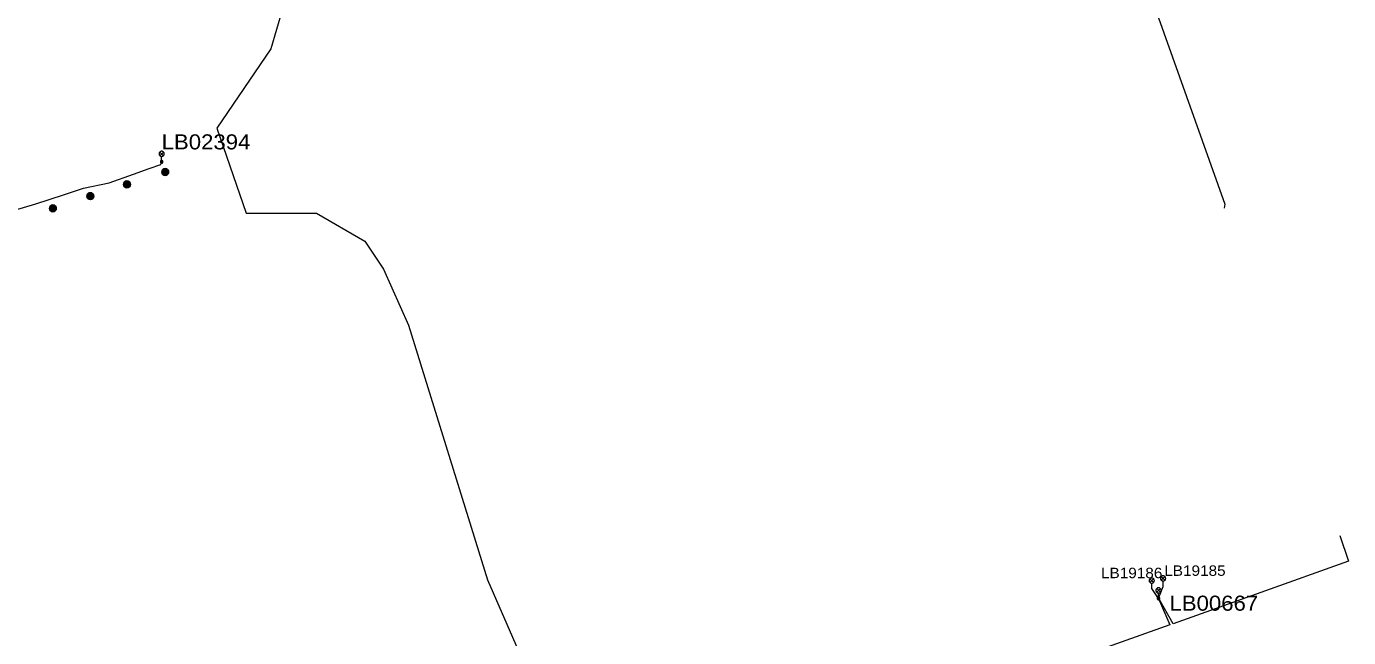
# Model space of a CAD drawing. Extents: x -688049 to -687261, y -973611 to -973038.
# Drawn here: x -687451.2 to -687260.9, y -973412.5 to -973324.5 of the extents above; entities that cross this region are included whole.
import ezdxf

# ---------------------------------------------------------------- set-up
doc = ezdxf.new("R2010")
doc.units = 0
doc.header["$LTSCALE"] = 0.87
doc.linetypes.add('LONG_DASH_SHORT_DASH', pattern=[9.9, 6, -1.2, 1.5, -1.2])
doc.layers.add('1', color=7, linetype='Continuous', lineweight=13)

msp = doc.modelspace()

# ---------------------------------------------------------------- hatches: boundary and pattern name
at = {"layer": '1'}
for points in [[(-687431.059, -973345.922, 1), (-687431.357, -973344.977, 1)], [(-687436.562, -973347.698, 1), (-687436.861, -973346.754, 1)], [(-687441.836, -973349.392, 1), (-687442.135, -973348.448, 1)], [(-687447.233, -973351.151, 1), (-687447.532, -973350.207, 1)]]:
    msp.add_hatch(color=256, dxfattribs=at).paths.add_polyline_path(points)

# ---------------------------------------------------------------- linework, layer by layer
for p, q in [((-687431.985, -973342.565), (-687431.455, -973343.095)), ((-687431.985, -973343.095), (-687431.455, -973342.565)), ((-687431.72, -973343.98), (-687431.72, -973343.205)), ((-687289.461, -973404.01), (-687288.931, -973404.54)), ((-687289.461, -973404.54), (-687288.931, -973404.01)), ((-687289.196, -973405.425), (-687289.196, -973404.65)), ((-687288.22, -973406.83), (-687287.559, -973405.098)), ((-687287.824, -973403.683), (-687287.294, -973404.213)), ((-687287.824, -973404.213), (-687287.294, -973403.683)), ((-687287.559, -973405.098), (-687287.559, -973404.323)), ((-687288.22, -973406.83), (-687289.196, -973405.425)), ((-687288.485, -973405.415), (-687287.955, -973405.945)), ((-687288.485, -973405.945), (-687287.955, -973405.415)), ((-687288.22, -973406.83), (-687288.22, -973406.055))]:
    msp.add_line(p, q, dxfattribs=at)
for points in [[(-687380.798, -973246.294), (-687379.608, -973246.294), (-687378.955, -973247.562), (-687376.887, -973255.287), (-687406.818, -973265.671), (-687416.352, -973274.485), (-687413.576, -973311.675), (-687413.576, -973319.312), (-687415.981, -973327.719), (-687423.796, -973339.13), (-687419.572, -973351.385), (-687409.434, -973351.385), (-687402.464, -973355.4), (-687399.787, -973359.445), (-687396.201, -973367.518), (-687384.836, -973404.179), (-687376.008, -973424.395), (-687374.353, -973427.776), (-687369.362, -973427.776), (-687366.818, -973426.737), (-687366.538, -973425.138)], [(-687288.9, -973322.19), (-687288.451, -973322.592), (-687278.691, -973350.089), (-687278.75, -973350.656)], [(-687262.11, -973397.78), (-687260.862, -973401.463), (-687286.115, -973410.499), (-687288.185, -973406.865)], [(-687288.22, -973406.83), (-687286.589, -973410.657), (-687312.448, -973419.852), (-687314.25, -973415.96)]]:
    msp.add_lwpolyline(points, dxfattribs=at)
at = {"layer": '1', "linetype": 'LONG_DASH_SHORT_DASH'}
msp.add_lwpolyline([(-687471.1, -973357.3), (-687469.23, -973356.72), (-687466.28, -973355.69), (-687461.51, -973353.91), (-687455.96, -973351.99), (-687452.92, -973350.95), (-687449.84, -973350.04), (-687445.86, -973348.71), (-687442.97, -973347.78), (-687439.3, -973347.01), (-687435.78, -973345.76), (-687433.52, -973344.93), (-687431.83, -973344.36), (-687431.72, -973343.98)], dxfattribs=at)
at = {"layer": '1'}
for points in [[(-687431.345, -973342.83), (-687431.351, -973342.765), (-687431.368, -973342.702), (-687431.395, -973342.643), (-687431.433, -973342.589), (-687431.479, -973342.543), (-687431.532, -973342.505), (-687431.592, -973342.478), (-687431.655, -973342.461), (-687431.72, -973342.455), (-687431.785, -973342.461), (-687431.848, -973342.478), (-687431.908, -973342.505), (-687431.961, -973342.543), (-687432.007, -973342.589), (-687432.045, -973342.643), (-687432.072, -973342.702), (-687432.089, -973342.765), (-687432.095, -973342.83), (-687432.089, -973342.895), (-687432.072, -973342.958), (-687432.045, -973343.018), (-687432.007, -973343.071), (-687431.961, -973343.117), (-687431.908, -973343.155), (-687431.848, -973343.182), (-687431.785, -973343.199), (-687431.72, -973343.205), (-687431.655, -973343.199), (-687431.592, -973343.182), (-687431.532, -973343.155), (-687431.479, -973343.117), (-687431.433, -973343.071), (-687431.395, -973343.018), (-687431.368, -973342.958), (-687431.351, -973342.895)], [(-687431.53, -973343.98), (-687431.533, -973343.947), (-687431.541, -973343.915), (-687431.555, -973343.885), (-687431.574, -973343.858), (-687431.598, -973343.834), (-687431.625, -973343.815), (-687431.655, -973343.801), (-687431.687, -973343.793), (-687431.72, -973343.79), (-687431.753, -973343.793), (-687431.785, -973343.801), (-687431.815, -973343.815), (-687431.842, -973343.834), (-687431.866, -973343.858), (-687431.885, -973343.885), (-687431.899, -973343.915), (-687431.907, -973343.947), (-687431.91, -973343.98), (-687431.907, -973344.013), (-687431.899, -973344.045), (-687431.885, -973344.075), (-687431.866, -973344.102), (-687431.842, -973344.126), (-687431.815, -973344.145), (-687431.785, -973344.159), (-687431.753, -973344.167), (-687431.72, -973344.17), (-687431.687, -973344.167), (-687431.655, -973344.159), (-687431.625, -973344.145), (-687431.598, -973344.126), (-687431.574, -973344.102), (-687431.555, -973344.075), (-687431.541, -973344.045), (-687431.533, -973344.013)], [(-687431.67, -973343.98), (-687431.671, -973343.971), (-687431.673, -973343.963), (-687431.677, -973343.955), (-687431.682, -973343.948), (-687431.688, -973343.942), (-687431.695, -973343.937), (-687431.703, -973343.933), (-687431.711, -973343.931), (-687431.72, -973343.93), (-687431.729, -973343.931), (-687431.737, -973343.933), (-687431.745, -973343.937), (-687431.752, -973343.942), (-687431.758, -973343.948), (-687431.763, -973343.955), (-687431.767, -973343.963), (-687431.769, -973343.971), (-687431.77, -973343.98), (-687431.769, -973343.989), (-687431.767, -973343.997), (-687431.763, -973344.005), (-687431.758, -973344.012), (-687431.752, -973344.018), (-687431.745, -973344.023), (-687431.737, -973344.027), (-687431.729, -973344.029), (-687431.72, -973344.03), (-687431.711, -973344.029), (-687431.703, -973344.027), (-687431.695, -973344.023), (-687431.688, -973344.018), (-687431.682, -973344.012), (-687431.677, -973344.005), (-687431.673, -973343.997), (-687431.671, -973343.989)], [(-687288.821, -973404.275), (-687288.827, -973404.21), (-687288.844, -973404.147), (-687288.871, -973404.088), (-687288.909, -973404.034), (-687288.955, -973403.988), (-687289.008, -973403.95), (-687289.068, -973403.923), (-687289.131, -973403.906), (-687289.196, -973403.9), (-687289.261, -973403.906), (-687289.324, -973403.923), (-687289.384, -973403.95), (-687289.437, -973403.988), (-687289.483, -973404.034), (-687289.521, -973404.088), (-687289.548, -973404.147), (-687289.565, -973404.21), (-687289.571, -973404.275), (-687289.565, -973404.34), (-687289.548, -973404.403), (-687289.521, -973404.462), (-687289.483, -973404.516), (-687289.437, -973404.562), (-687289.384, -973404.6), (-687289.324, -973404.627), (-687289.261, -973404.644), (-687289.196, -973404.65), (-687289.131, -973404.644), (-687289.068, -973404.627), (-687289.008, -973404.6), (-687288.955, -973404.562), (-687288.909, -973404.516), (-687288.871, -973404.462), (-687288.844, -973404.403), (-687288.827, -973404.34)], [(-687287.184, -973403.948), (-687287.19, -973403.883), (-687287.207, -973403.82), (-687287.234, -973403.76), (-687287.272, -973403.707), (-687287.318, -973403.661), (-687287.372, -973403.623), (-687287.431, -973403.596), (-687287.494, -973403.579), (-687287.559, -973403.573), (-687287.624, -973403.579), (-687287.687, -973403.596), (-687287.746, -973403.623), (-687287.8, -973403.661), (-687287.846, -973403.707), (-687287.884, -973403.76), (-687287.911, -973403.82), (-687287.928, -973403.883), (-687287.934, -973403.948), (-687287.928, -973404.013), (-687287.911, -973404.076), (-687287.884, -973404.136), (-687287.846, -973404.189), (-687287.8, -973404.235), (-687287.746, -973404.273), (-687287.687, -973404.3), (-687287.624, -973404.317), (-687287.559, -973404.323), (-687287.494, -973404.317), (-687287.431, -973404.3), (-687287.372, -973404.273), (-687287.318, -973404.235), (-687287.272, -973404.189), (-687287.234, -973404.136), (-687287.207, -973404.076), (-687287.19, -973404.013)], [(-687287.845, -973405.68), (-687287.851, -973405.615), (-687287.868, -973405.552), (-687287.895, -973405.492), (-687287.933, -973405.439), (-687287.979, -973405.393), (-687288.032, -973405.355), (-687288.092, -973405.328), (-687288.155, -973405.311), (-687288.22, -973405.305), (-687288.285, -973405.311), (-687288.348, -973405.328), (-687288.408, -973405.355), (-687288.461, -973405.393), (-687288.507, -973405.439), (-687288.545, -973405.492), (-687288.572, -973405.552), (-687288.589, -973405.615), (-687288.595, -973405.68), (-687288.589, -973405.745), (-687288.572, -973405.808), (-687288.545, -973405.867), (-687288.507, -973405.921), (-687288.461, -973405.967), (-687288.408, -973406.005), (-687288.348, -973406.032), (-687288.285, -973406.049), (-687288.22, -973406.055), (-687288.155, -973406.049), (-687288.092, -973406.032), (-687288.032, -973406.005), (-687287.979, -973405.967), (-687287.933, -973405.921), (-687287.895, -973405.867), (-687287.868, -973405.808), (-687287.851, -973405.745)], [(-687288.03, -973406.83), (-687288.033, -973406.797), (-687288.041, -973406.765), (-687288.055, -973406.735), (-687288.074, -973406.708), (-687288.098, -973406.684), (-687288.125, -973406.665), (-687288.155, -973406.651), (-687288.187, -973406.643), (-687288.22, -973406.64), (-687288.253, -973406.643), (-687288.285, -973406.651), (-687288.315, -973406.665), (-687288.342, -973406.684), (-687288.366, -973406.708), (-687288.385, -973406.735), (-687288.399, -973406.765), (-687288.407, -973406.797), (-687288.41, -973406.83), (-687288.407, -973406.863), (-687288.399, -973406.895), (-687288.385, -973406.925), (-687288.366, -973406.952), (-687288.342, -973406.976), (-687288.315, -973406.995), (-687288.285, -973407.009), (-687288.253, -973407.017), (-687288.22, -973407.02), (-687288.187, -973407.017), (-687288.155, -973407.009), (-687288.125, -973406.995), (-687288.098, -973406.976), (-687288.074, -973406.952), (-687288.055, -973406.925), (-687288.041, -973406.895), (-687288.033, -973406.863)], [(-687288.17, -973406.83), (-687288.171, -973406.821), (-687288.173, -973406.813), (-687288.177, -973406.805), (-687288.182, -973406.798), (-687288.188, -973406.792), (-687288.195, -973406.787), (-687288.203, -973406.783), (-687288.211, -973406.781), (-687288.22, -973406.78), (-687288.229, -973406.781), (-687288.237, -973406.783), (-687288.245, -973406.787), (-687288.252, -973406.792), (-687288.258, -973406.798), (-687288.263, -973406.805), (-687288.267, -973406.813), (-687288.269, -973406.821), (-687288.27, -973406.83), (-687288.269, -973406.839), (-687288.267, -973406.847), (-687288.263, -973406.855), (-687288.258, -973406.862), (-687288.252, -973406.868), (-687288.245, -973406.873), (-687288.237, -973406.877), (-687288.229, -973406.879), (-687288.22, -973406.88), (-687288.211, -973406.879), (-687288.203, -973406.877), (-687288.195, -973406.873), (-687288.188, -973406.868), (-687288.182, -973406.862), (-687288.177, -973406.855), (-687288.173, -973406.847), (-687288.171, -973406.839)]]:
    msp.add_lwpolyline(points, close=True, dxfattribs=at)
at = {"layer": '1', "lineweight": 25}
for centre in [(-687431.208, -973345.449), (-687436.712, -973347.226), (-687441.986, -973348.92), (-687447.383, -973350.679)]:
    msp.add_circle(centre, 0.495, dxfattribs=at)

# ---------------------------------------------------------------- texts
at = {"layer": '1', "width": 1.1}
for s, height, p in [('LB02394', 2.168, (-687431.72, -973342.192)), ('LB19186', 1.5, (-687296.501, -973403.917)), ('LB19185', 1.5, (-687287.391, -973403.583)), ('LB00667', 2.167, (-687286.639, -973408.602))]:
    msp.add_text(s, height=height, dxfattribs=at).set_placement(p)

doc.saveas('drawing.dxf')
